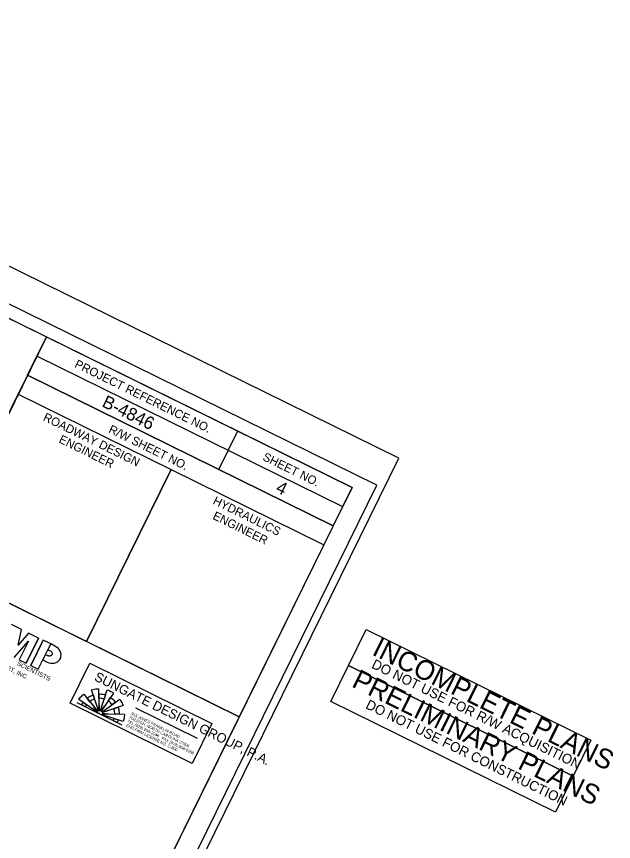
# Model space of a CAD drawing. Extents: x 1428420 to 1430540, y 857897 to 859622.
# Drawn here: x 1430189.5 to 1430540.2, y 858654.2 to 859138.3 of the extents above; entities that cross this region are included whole.
import ezdxf

# ---------------------------------------------------------------- set-up
doc = ezdxf.new("R2010")
doc.units = 0
for name, color, linetype in [('Old_Level_43', 7, 'Continuous'), ('Old_Level_51', 7, 'Continuous'), ('Sheet Data Field CELL', 7, 'Continuous'), ('Sheet Plan CELL', 7, 'Continuous'), ('Sheet Plot Border Inside CELL', 7, 'Continuous'), ('Sheet Plot Border Outside CELL', 7, 'Continuous'), ('Sheet Sticker Incomplete CELL', 7, 'Continuous'), ('Sheet Sticker Preliminary CELL', 7, 'Continuous')]:
    doc.layers.add(name, color=color, linetype=linetype)

msp = doc.modelspace()

# ---------------------------------------------------------------- linework, layer by layer
at = {"layer": 'Old_Level_51'}
for p, q in [((1430192.45, 858778.56), (1430186.53, 858781.47)), ((1430190.51, 858769.5), (1430192.45, 858778.56)), ((1430196.58, 858776.53), (1430190.51, 858769.5)), ((1430202.5, 858773.61), (1430196.58, 858776.53)), ((1430188.23, 858762.27), (1430196.48, 858771.79)), ((1430196.48, 858771.79), (1430191.1, 858760.86)), ((1430202.5, 858773.61), (1430195.23, 858758.83)), ((1430195.23, 858758.83), (1430202.5, 858773.61)), ((1430197.86, 858757.54), (1430205.13, 858772.32)), ((1430205.13, 858772.32), (1430197.86, 858757.54)), ((1430209.6, 858770.12), (1430205.13, 858772.32)), ((1430206.54, 858763.89), (1430207.93, 858766.72)), ((1430207.93, 858766.72), (1430209.6, 858770.12)), ((1430209.6, 858770.12), (1430207.93, 858766.72)), ((1430207.93, 858766.72), (1430209.3, 858766.04)), ((1430209.3, 858766.04), (1430209.61, 858765.89)), ((1430212.12, 858768.88), (1430209.6, 858770.12)), ((1430209.61, 858765.89), (1430209.86, 858765.72)), ((1430209.86, 858765.72), (1430210.14, 858765.44)), ((1430210.14, 858765.44), (1430210.3, 858765.17)), ((1430213.04, 858768.33), (1430212.12, 858768.88)), ((1430213.96, 858767.6), (1430213.04, 858768.33)), ((1430214.57, 858766.82), (1430213.96, 858767.6)), ((1430215.17, 858765.81), (1430214.57, 858766.82)), ((1430215.52, 858764.88), (1430215.17, 858765.81)), ((1430191.1, 858760.86), (1430195.23, 858758.83)), ((1430202.33, 858755.34), (1430205, 858760.76)), ((1430205, 858760.76), (1430206.54, 858763.89)), ((1430206.54, 858763.89), (1430205, 858760.76)), ((1430205, 858760.76), (1430207.52, 858759.52)), ((1430207.91, 858763.22), (1430206.54, 858763.89)), ((1430208.24, 858763.11), (1430207.91, 858763.22)), ((1430208.52, 858763.01), (1430208.24, 858763.11)), ((1430208.94, 858762.99), (1430208.52, 858763.01)), ((1430209.27, 858763.07), (1430208.94, 858762.99)), ((1430209.61, 858763.09), (1430209.27, 858763.07)), ((1430209.84, 858763.27), (1430209.61, 858763.09)), ((1430210.07, 858763.44), (1430209.84, 858763.27)), ((1430210.25, 858763.63), (1430210.07, 858763.44)), ((1430210.39, 858763.9), (1430210.25, 858763.63)), ((1430210.3, 858765.17), (1430210.45, 858764.81)), ((1430210.44, 858764.2), (1430210.39, 858763.9)), ((1430210.47, 858764.56), (1430210.44, 858764.2)), ((1430210.45, 858764.81), (1430210.47, 858764.56)), ((1430214.44, 858760.39), (1430215.06, 858761.07)), ((1430215.06, 858761.07), (1430215.52, 858761.99)), ((1430215.69, 858763.89), (1430215.52, 858764.88)), ((1430215.52, 858761.99), (1430215.66, 858762.87)), ((1430215.66, 858762.87), (1430215.69, 858763.89)), ((1430197.86, 858757.54), (1430202.33, 858755.34)), ((1430207.52, 858759.52), (1430208.51, 858759.13)), ((1430208.51, 858759.13), (1430209.67, 858758.89)), ((1430209.67, 858758.89), (1430210.64, 858758.83)), ((1430210.64, 858758.83), (1430211.77, 858758.9)), ((1430211.77, 858758.9), (1430212.73, 858759.23)), ((1430212.73, 858759.23), (1430213.63, 858759.7)), ((1430213.63, 858759.7), (1430214.44, 858760.39)), ((1430237.98, 858738.24), (1430237.98, 858738.24)), ((1430225.05, 858735.69), (1430251.41, 858722.72)), ((1430229.68, 858735.1), (1430229.68, 858735.1)), ((1430236.67, 858730.28), (1430233.9, 858732.2)), ((1430237.05, 858730.69), (1430234.95, 858733.31)), ((1430235.52, 858732.6), (1430235.52, 858732.6)), ((1430236.56, 858734.19), (1430237.63, 858731)), ((1430238.17, 858731.1), (1430238.06, 858734.46)), ((1430238.81, 858731.01), (1430239.84, 858734.21)), ((1430239.31, 858730.77), (1430241.22, 858733.53)), ((1430239.77, 858730.31), (1430242.5, 858732.28)), ((1430245.57, 858734.5), (1430245.57, 858734.5)), ((1430259.5, 858732.61), (1430295.55, 858714.87)), ((1430243.2, 858730.92), (1430240.02, 858729.82)), ((1430240.04, 858728.63), (1430243.24, 858727.6)), ((1430242.07, 858729.14), (1430240.13, 858729.17)), ((1430240.13, 858729.17), (1430243.49, 858729.11))]:
    msp.add_line(p, q, dxfattribs=at)
for points in [[(1430232.55, 858758.83), (1430304.33, 858723.51), (1430292.76, 858700), (1430220.98, 858735.32)], [(1430237.63, 858731), (1430233.55, 858743.13), (1430234.35, 858743.37), (1430235.21, 858743.58), (1430236.03, 858743.73), (1430236.92, 858743.83), (1430237.77, 858743.89), (1430238.17, 858731.1)], [(1430238.81, 858731.01), (1430242.71, 858743.19), (1430243.49, 858742.92), (1430244.33, 858742.57), (1430245.02, 858742.23), (1430245.84, 858741.77), (1430246.58, 858741.29), (1430239.31, 858730.77)], [(1430236.67, 858730.28), (1430226.14, 858737.55), (1430226.6, 858738.18), (1430227.34, 858739.06), (1430227.83, 858739.58), (1430228.51, 858740.22), (1430229.05, 858740.67), (1430237.05, 858730.69)], [(1430230.98, 858738.26), (1430231.56, 858738.7), (1430232.05, 858739.03), (1430232.66, 858739.38), (1430233.22, 858739.67), (1430233.83, 858739.94), (1430234.54, 858740.2), (1430235.36, 858737.77), (1430234.76, 858737.54), (1430234.27, 858737.32), (1430233.79, 858737.07), (1430233.28, 858736.76), (1430232.9, 858736.49), (1430232.58, 858736.25)], [(1430237.86, 858740.8), (1430238.48, 858740.81), (1430239.39, 858740.75), (1430240.34, 858740.62), (1430241.15, 858740.43), (1430241.77, 858740.25), (1430240.99, 858737.8), (1430240.4, 858737.97), (1430239.83, 858738.09), (1430239.22, 858738.18), (1430238.56, 858738.23), (1430237.95, 858738.23)], [(1430239.77, 858730.31), (1430250.14, 858737.8), (1430250.69, 858736.99), (1430251.24, 858736.01), (1430251.57, 858735.35), (1430251.86, 858734.68), (1430252.11, 858734), (1430240.02, 858729.82)], [(1430244.82, 858738.75), (1430245.39, 858738.33), (1430246.02, 858737.81), (1430246.61, 858737.23), (1430247.13, 858736.65), (1430247.64, 858735.99), (1430245.55, 858734.49), (1430245.26, 858734.87), (1430244.86, 858735.33), (1430244.25, 858735.93), (1430243.8, 858736.31), (1430243.36, 858736.64)], [(1430227.82, 858734.33), (1430228.05, 858734.78), (1430228.35, 858735.29), (1430228.68, 858735.79), (1430230.8, 858734.33), (1430230.56, 858733.97), (1430230.34, 858733.59), (1430230.13, 858733.19)], [(1430249.2, 858732.99), (1430249.4, 858732.34), (1430249.57, 858731.65), (1430249.7, 858730.96), (1430249.81, 858729.99), (1430249.83, 858729), (1430247.26, 858729.05), (1430247.25, 858729.69), (1430247.17, 858730.45), (1430247.08, 858731), (1430246.97, 858731.49), (1430246.77, 858732.15)], [(1430236.53, 858730.04), (1430236.6, 858730.17), (1430236.67, 858730.28), (1430236.86, 858730.52), (1430237.05, 858730.69), (1430237.2, 858730.8), (1430237.37, 858730.89), (1430237.51, 858730.96), (1430237.63, 858731), (1430237.9, 858731.07), (1430238.17, 858731.1), (1430238.34, 858731.1), (1430238.53, 858731.08), (1430238.7, 858731.04), (1430238.81, 858731.01), (1430239.07, 858730.91), (1430239.31, 858730.77), (1430239.44, 858730.67), (1430239.55, 858730.57), (1430239.66, 858730.46), (1430239.77, 858730.31), (1430239.91, 858730.08), (1430240.02, 858729.82), (1430240.07, 858729.68), (1430240.1, 858729.51), (1430240.12, 858729.36), (1430240.13, 858729.17), (1430240.1, 858728.88), (1430240.04, 858728.63), (1430239.99, 858728.49), (1430239.93, 858728.37)], [(1430240.12, 858729.16), (1430252.92, 858728.94), (1430252.89, 858728.27), (1430252.82, 858727.49), (1430252.69, 858726.62), (1430252.55, 858725.95), (1430252.22, 858724.72), (1430240.04, 858728.63)], [(1430249.28, 858725.66), (1430248.98, 858724.83), (1430248.65, 858724.1), (1430246.33, 858725.22), (1430246.6, 858725.82), (1430246.83, 858726.45)]]:
    msp.add_lwpolyline(points, close=True, dxfattribs=at)
for start, end in [(153.8001, 333.8001), (333.8001, 153.8001)]:
    msp.add_arc((1430272.02, 858716.57), 0.082, start, end, dxfattribs=at)
at = {"layer": 'Sheet Plan CELL'}
for p, q in [((1430201.6, 858939.09), (1430381.09, 858850.76)), ((1430196.08, 858927.84), (1430190.56, 858916.63)), ((1430196.08, 858927.84), (1430375.57, 858839.54)), ((1430196.08, 858927.84), (1430375.57, 858839.54)), ((1430319.29, 858895.08), (1430308.3, 858872.63)), ((1430280.34, 858872.46), (1430230.69, 858771.54))]:
    msp.add_line(p, q, dxfattribs=at)
for points in [[(1430386.67, 858862), (1429040.75, 859524.27), (1428581.58, 858591.12), (1429927.48, 857928.86)], [(1428581.58, 858591.12), (1429040.71, 859524.26), (1430207.15, 858950.35), (1430140.91, 858815.69), (1430320.39, 858727.37), (1429927.48, 857928.86)], [(1430207.15, 858950.35), (1430386.67, 858862), (1430375.57, 858839.54), (1430196.08, 858927.84)], [(1430190.56, 858916.63), (1430280.34, 858872.46), (1430230.66, 858771.51), (1430140.91, 858815.69)], [(1430280.34, 858872.46), (1430370.06, 858828.32), (1430320.39, 858727.37), (1430230.66, 858771.51)]]:
    msp.add_lwpolyline(points, close=True, dxfattribs=at)
at = {"layer": 'Sheet Plot Border Inside CELL'}
msp.add_lwpolyline([(1428440.55, 858652.15), (1429935.37, 857916.62), (1430401.17, 858863.21), (1428906.33, 859598.76)], close=True, dxfattribs=at)
at = {"layer": 'Sheet Plot Border Outside CELL'}
msp.add_lwpolyline([(1428420.05, 858639.94), (1429930.59, 857896.67), (1430414.03, 858879.17), (1428903.5, 859622.44)], close=True, dxfattribs=at)
at = {"layer": 'Sheet Sticker Incomplete CELL'}
msp.add_lwpolyline([(1430384.55, 858757.45), (1430394.92, 858778.54), (1430526.82, 858713.64), (1430516.44, 858692.55)], close=True, dxfattribs=at)
at = {"layer": 'Sheet Sticker Preliminary CELL'}
msp.add_lwpolyline([(1430374.17, 858736.37), (1430384.55, 858757.45), (1430516.44, 858692.55), (1430506.07, 858671.47)], close=True, dxfattribs=at)

# ---------------------------------------------------------------- texts
at = {"layer": 'Old_Level_43'}
msp.add_text('DYER, RIDDLE, MILLS & PRECOURT, INC.', height=2.6268, rotation=333.8001, dxfattribs=at).set_placement((1430131.24, 858780.9))
at = {"layer": 'Old_Level_51'}
for s, height, p in [('SCIENTISTS', 2.627, (1430189.57, 858757.77)), ('SUNGATE DESIGN GROUP, P.A.', 5.5473, (1430234.79, 858748.97)), ('RALEIGH, NORTH CAROLINA 27606', 1.6671, (1430255.66, 858726.44)), ('915 JONES FRANKLIN ROAD', 1.6671, (1430256.75, 858728.64)), ('ENG FIRM LICENSE NO. C-890', 1.6671, (1430253.69, 858721.77)), ('TEL (919) 859-2243   FAX (919) 859-6258', 1.6671, (1430254.39, 858724.24))]:
    msp.add_text(s, height=height, rotation=333.8001, dxfattribs=at).set_placement(p)
at = {"layer": 'Sheet Data Field CELL'}
for s, p in [('B-4846', (1430239.18, 858909.71)), ('4', (1430341.23, 858859.56))]:
    msp.add_text(s, height=7.5, rotation=333.8001, dxfattribs=at).set_placement(p)
at = {"layer": 'Sheet Plan CELL'}
for s, height, p in [('PROJECT REFERENCE NO.', 5.0001, (1430223.22, 858932.72)), ('ROADWAY DESIGN', 5.0001, (1430204.73, 858901.53)), ('R/W SHEET NO.', 5.0001, (1430243.17, 858894.43)), ('ENGINEER', 5, (1430213.95, 858888.59)), ('SHEET NO.', 5, (1430333.68, 858878.24)), ('HYDRAULICS', 5, (1430304.46, 858852.48)), ('ENGINEER', 5, (1430304.32, 858843.68))]:
    msp.add_text(s, height=height, rotation=333.8001, dxfattribs=at).set_placement(p)
at = {"layer": 'Sheet Sticker Incomplete CELL'}
for s, height, p in [('INCOMPLETE PLANS', 11.52, (1430397.74, 858764)), ('DO NOT USE FOR R/W ACQUISITION', 5.76, (1430397.59, 858756.33))]:
    msp.add_text(s, height=height, rotation=333.8001, dxfattribs=at).set_placement(p)
at = {"layer": 'Sheet Sticker Preliminary CELL'}
for s, height, p in [('PRELIMINARY PLANS', 11.52, (1430385.81, 858745.3)), ('DO NOT USE FOR CONSTRUCTION', 5.76, (1430394.16, 858732.6))]:
    msp.add_text(s, height=height, rotation=333.8001, dxfattribs=at).set_placement(p)

doc.saveas('drawing.dxf')
